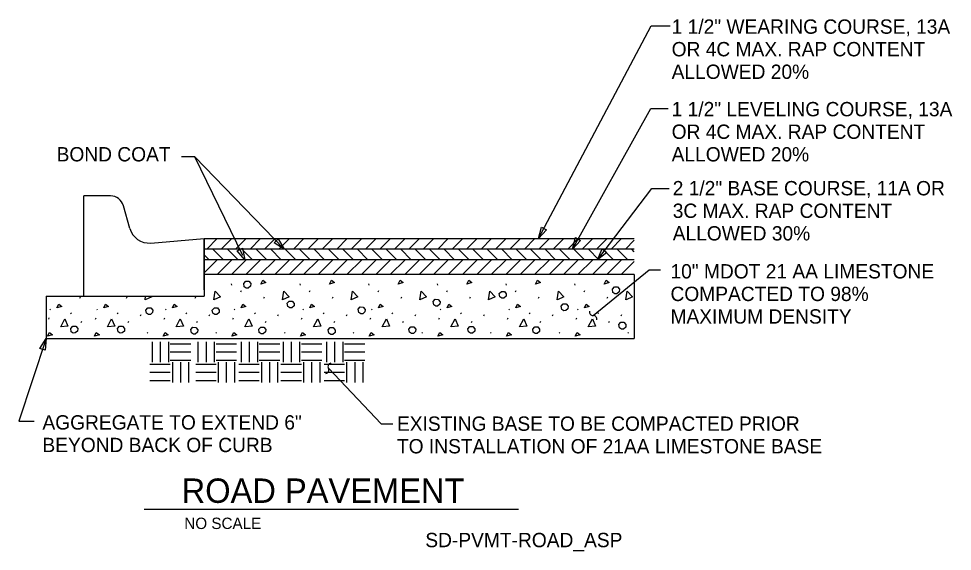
# Model space of a CAD drawing. Extents: x 9879.1 to 9947.1, y 9983.9 to 10022.7.
import ezdxf

# ---------------------------------------------------------------- set-up
doc = ezdxf.new("R2010")
doc.units = 0
for name, color, linetype in [('G-ANNO-TEXT', 7, 'Continuous'), ('G-DETL-LINE', 7, 'Continuous'), ('G-DETL-OTLN', 7, 'Continuous'), ('G-DETL-PATT', 7, 'Continuous')]:
    doc.layers.add(name, color=color, linetype=linetype)

msp = doc.modelspace()

# ---------------------------------------------------------------- linework, layer by layer
at = {"layer": 'G-ANNO-TEXT'}
for p, q in [((9892.6, 10005.594), (9892.6, 10006.669)), ((9892.6, 10004.685), (9892.6, 10005.594)), ((9888.222, 9986.949), (9915.472, 9986.949))]:
    msp.add_line(p, q, dxfattribs=at)
for points in [[(9916.941, 10006.675), (9925.138, 10022.152), (9926.513, 10022.152)], [(9919.408, 10005.906), (9925.121, 10016.137), (9926.384, 10016.137)], [(9895.409, 10005.432), (9891.922, 10012.612), (9890.939, 10012.612)], [(9898.415, 10005.898), (9891.922, 10012.612), (9891.922, 10012.612)], [(9921.247, 10005.132), (9925.193, 10010.313), (9926.437, 10010.313)]]:
    msp.add_lwpolyline(points, dxfattribs=at)
for points in [[(9917.515, 10007.314), (9916.941, 10006.675), (9917.147, 10007.509)], [(9897.985, 10006.642), (9898.415, 10005.898), (9897.686, 10006.352)], [(9919.997, 10006.532), (9919.408, 10005.906), (9919.633, 10006.735)], [(9895.38, 10005.969), (9895.557, 10005.128), (9895.006, 10005.787)], [(9921.908, 10005.659), (9921.237, 10005.123), (9921.577, 10005.912)]]:
    msp.add_lwpolyline(points, close=True, dxfattribs=at)
at = {"layer": 'G-DETL-LINE'}
for p, q in [((9892.6, 10006.669), (9923.906, 10006.669)), ((9923.906, 10005.899), (9892.6, 10005.899)), ((9923.906, 10005.128), (9892.6, 10005.128)), ((9923.906, 10004.054), (9892.6, 10004.054)), ((9923.906, 10004.054), (9923.906, 9999.397)), ((9881.093, 10002.467), (9881.093, 9999.397)), ((9881.093, 10002.467), (9883.832, 10002.467)), ((9881.093, 9999.397), (9923.906, 9999.397))]:
    msp.add_line(p, q, dxfattribs=at)
for points in [[(9920.908, 10001.064), (9924.979, 10004.38), (9925.807, 10004.38)], [(9881.093, 9999.397), (9879.087, 9993.37), (9880.204, 9993.37)], [(9901.636, 9997.221), (9905.48, 9993.165), (9906.339, 9993.165)]]:
    msp.add_lwpolyline(points, dxfattribs=at)
msp.add_lwpolyline([(9880.632, 9998.672), (9881.093, 9999.397), (9881.028, 9998.54)], close=True, dxfattribs=at)
for centre, start, end in [((9920.898, 10001.324), 166.03521, 272.29541), ((9920.918, 10000.804), 346.03521, 92.29541), ((9901.407, 9997.097), 281.95462, 28.21482), ((9901.866, 9997.344), 101.95462, 208.21482)]:
    msp.add_arc(centre, 0.26, start, end, dxfattribs=at)
at = {"layer": 'G-DETL-OTLN'}
for p, q in [((9885.775, 10009.774), (9883.832, 10009.774)), ((9883.832, 10002.467), (9883.832, 10009.774)), ((9887.175, 10007.408), (9886.714, 10009.062)), ((9888.704, 10006.344), (9892.6, 10006.669)), ((9892.6, 10002.923), (9892.6, 10006.669)), ((9892.6, 10006.669), (9892.6, 10002.467)), ((9883.832, 10002.467), (9892.6, 10002.467))]:
    msp.add_line(p, q, dxfattribs=at)
for centre, radius, start, end in [((9885.775, 10008.8), 0.974, 15.57142, 90), ((9888.582, 10007.801), 1.461, 195.57137, 274.76366)]:
    msp.add_arc(centre, radius, start, end, dxfattribs=at)
at = {"layer": 'G-DETL-PATT'}
for p, q in [((9892.78, 10005.899), (9893.55, 10006.669)), ((9893.831, 10005.899), (9894.601, 10006.669)), ((9894.882, 10005.899), (9895.652, 10006.669)), ((9895.933, 10005.899), (9896.703, 10006.669)), ((9896.984, 10005.899), (9897.755, 10006.669)), ((9898.035, 10005.899), (9898.806, 10006.669)), ((9899.087, 10005.899), (9899.857, 10006.669)), ((9900.138, 10005.899), (9900.908, 10006.669)), ((9901.189, 10005.899), (9901.959, 10006.669)), ((9902.24, 10005.899), (9903.01, 10006.669)), ((9903.291, 10005.899), (9904.061, 10006.669)), ((9904.342, 10005.899), (9905.113, 10006.669)), ((9905.393, 10005.899), (9906.164, 10006.669)), ((9906.445, 10005.899), (9907.215, 10006.669)), ((9907.496, 10005.899), (9908.266, 10006.669)), ((9908.547, 10005.899), (9909.317, 10006.669)), ((9909.598, 10005.899), (9910.368, 10006.669)), ((9910.649, 10005.899), (9911.419, 10006.669)), ((9911.7, 10005.899), (9912.47, 10006.669)), ((9912.751, 10005.899), (9913.522, 10006.669)), ((9913.802, 10005.899), (9914.573, 10006.669)), ((9914.854, 10005.899), (9915.624, 10006.669)), ((9915.905, 10005.899), (9916.675, 10006.669)), ((9916.956, 10005.899), (9917.726, 10006.669)), ((9918.007, 10005.899), (9918.777, 10006.669)), ((9919.058, 10005.899), (9919.828, 10006.669)), ((9920.109, 10005.899), (9920.88, 10006.669)), ((9921.16, 10005.899), (9921.931, 10006.669)), ((9922.212, 10005.899), (9922.982, 10006.669)), ((9894.006, 10005.128), (9893.235, 10005.899)), ((9895.057, 10005.128), (9894.286, 10005.899)), ((9896.108, 10005.128), (9895.338, 10005.899)), ((9897.159, 10005.128), (9896.389, 10005.899)), ((9898.21, 10005.128), (9897.44, 10005.899)), ((9899.261, 10005.128), (9898.491, 10005.899)), ((9900.313, 10005.128), (9899.542, 10005.899)), ((9901.364, 10005.128), (9900.593, 10005.899)), ((9902.415, 10005.128), (9901.644, 10005.899)), ((9903.466, 10005.128), (9902.696, 10005.899)), ((9904.517, 10005.128), (9903.747, 10005.899)), ((9905.568, 10005.128), (9904.798, 10005.899)), ((9906.619, 10005.128), (9905.849, 10005.899)), ((9907.671, 10005.128), (9906.9, 10005.899)), ((9908.722, 10005.128), (9907.951, 10005.899)), ((9909.773, 10005.128), (9909.002, 10005.899)), ((9910.824, 10005.128), (9910.054, 10005.899)), ((9911.875, 10005.128), (9911.105, 10005.899)), ((9912.926, 10005.128), (9912.156, 10005.899)), ((9913.977, 10005.128), (9913.207, 10005.899)), ((9915.028, 10005.128), (9914.258, 10005.899)), ((9916.08, 10005.128), (9915.309, 10005.899)), ((9917.131, 10005.128), (9916.36, 10005.899)), ((9918.182, 10005.128), (9917.411, 10005.899)), ((9919.233, 10005.128), (9918.462, 10005.899)), ((9920.284, 10005.128), (9919.514, 10005.899)), ((9921.335, 10005.128), (9920.565, 10005.899)), ((9922.386, 10005.128), (9921.616, 10005.899)), ((9923.437, 10005.128), (9922.667, 10005.899)), ((9923.263, 10005.899), (9923.906, 10006.542)), ((9923.906, 10005.711), (9923.718, 10005.899)), ((9892.955, 10005.128), (9892.6, 10005.482)), ((9892.6, 10004.179), (9893.55, 10005.128)), ((9893.527, 10004.054), (9894.601, 10005.128)), ((9894.578, 10004.054), (9895.652, 10005.128)), ((9895.629, 10004.054), (9896.703, 10005.128)), ((9896.68, 10004.054), (9897.755, 10005.128)), ((9897.731, 10004.054), (9898.806, 10005.128)), ((9898.782, 10004.054), (9899.857, 10005.128)), ((9899.834, 10004.054), (9900.908, 10005.128)), ((9900.885, 10004.054), (9901.959, 10005.128)), ((9901.936, 10004.054), (9903.01, 10005.128)), ((9902.987, 10004.054), (9904.061, 10005.128)), ((9904.038, 10004.054), (9905.113, 10005.128)), ((9905.089, 10004.054), (9906.164, 10005.128)), ((9906.14, 10004.054), (9907.215, 10005.128)), ((9907.192, 10004.054), (9908.266, 10005.128)), ((9908.243, 10004.054), (9909.317, 10005.128)), ((9909.294, 10004.054), (9910.368, 10005.128)), ((9910.345, 10004.054), (9911.419, 10005.128)), ((9911.396, 10004.054), (9912.47, 10005.128)), ((9912.447, 10004.054), (9913.522, 10005.128)), ((9913.498, 10004.054), (9914.573, 10005.128)), ((9914.549, 10004.054), (9915.624, 10005.128)), ((9915.601, 10004.054), (9916.675, 10005.128)), ((9916.652, 10004.054), (9917.726, 10005.128)), ((9917.703, 10004.054), (9918.777, 10005.128)), ((9918.754, 10004.054), (9919.828, 10005.128)), ((9919.805, 10004.054), (9920.88, 10005.128)), ((9920.856, 10004.054), (9921.931, 10005.128)), ((9921.907, 10004.054), (9922.982, 10005.128)), ((9922.958, 10004.054), (9923.906, 10005.001)), ((9894.565, 10003.366), (9894.576, 10003.266)), ((9899.565, 10003.366), (9899.576, 10003.266)), ((9904.565, 10003.366), (9904.576, 10003.266)), ((9909.565, 10003.366), (9909.576, 10003.266)), ((9914.565, 10003.366), (9914.576, 10003.266)), ((9919.565, 10003.366), (9919.576, 10003.266)), ((9895.257, 10002.777), (9895.301, 10002.877)), ((9900.257, 10002.777), (9900.301, 10002.877)), ((9905.257, 10002.777), (9905.301, 10002.877)), ((9910.257, 10002.777), (9910.301, 10002.877)), ((9915.257, 10002.777), (9915.301, 10002.877)), ((9920.257, 10002.777), (9920.301, 10002.877)), ((9883.532, 10002.322), (9883.577, 10002.422)), ((9886.944, 10002.322), (9886.988, 10002.422)), ((9891.944, 10002.322), (9891.988, 10002.422)), ((9896.944, 10002.322), (9896.988, 10002.422)), ((9901.944, 10002.322), (9901.988, 10002.422)), ((9906.944, 10002.322), (9906.988, 10002.422)), ((9911.944, 10002.322), (9911.988, 10002.422)), ((9916.944, 10002.322), (9916.988, 10002.422)), ((9921.944, 10002.322), (9921.988, 10002.422)), ((9881.358, 10001.534), (9881.403, 10001.468)), ((9882.854, 10001.252), (9882.898, 10001.185)), ((9884.77, 10001.534), (9884.814, 10001.468)), ((9886.265, 10001.252), (9886.309, 10001.185)), ((9887.954, 10001.035), (9887.998, 10001.134)), ((9889.77, 10001.534), (9889.814, 10001.468)), ((9891.265, 10001.252), (9891.309, 10001.185)), ((9892.954, 10001.035), (9892.998, 10001.134)), ((9894.77, 10001.534), (9894.814, 10001.468)), ((9896.265, 10001.252), (9896.309, 10001.185)), ((9897.954, 10001.035), (9897.998, 10001.134)), ((9899.77, 10001.534), (9899.814, 10001.468)), ((9901.265, 10001.252), (9901.309, 10001.185)), ((9902.954, 10001.035), (9902.998, 10001.134)), ((9904.77, 10001.534), (9904.814, 10001.468)), ((9906.265, 10001.252), (9906.309, 10001.185)), ((9907.954, 10001.035), (9907.998, 10001.134)), ((9909.77, 10001.534), (9909.814, 10001.468)), ((9911.265, 10001.252), (9911.309, 10001.185)), ((9912.954, 10001.035), (9912.998, 10001.134)), ((9914.77, 10001.534), (9914.814, 10001.468)), ((9916.265, 10001.252), (9916.309, 10001.185)), ((9917.954, 10001.035), (9917.998, 10001.134)), ((9919.77, 10001.534), (9919.814, 10001.468)), ((9921.265, 10001.252), (9921.294, 10001.208)), ((9921.301, 10001.198), (9921.309, 10001.185)), ((9922.954, 10001.035), (9922.998, 10001.134)), ((9881.274, 10000.803), (9881.319, 10000.903)), ((9883.643, 10000.547), (9883.688, 10000.647)), ((9884.686, 10000.803), (9884.73, 10000.903)), ((9887.055, 10000.547), (9887.099, 10000.647)), ((9889.686, 10000.803), (9889.73, 10000.903)), ((9892.055, 10000.547), (9892.099, 10000.647)), ((9894.686, 10000.803), (9894.73, 10000.903)), ((9897.055, 10000.547), (9897.099, 10000.647)), ((9899.686, 10000.803), (9899.73, 10000.903)), ((9902.055, 10000.547), (9902.099, 10000.647)), ((9904.686, 10000.803), (9904.73, 10000.903)), ((9907.055, 10000.547), (9907.099, 10000.647)), ((9909.686, 10000.803), (9909.73, 10000.903)), ((9912.055, 10000.547), (9912.099, 10000.647)), ((9914.686, 10000.803), (9914.73, 10000.903)), ((9917.055, 10000.547), (9917.099, 10000.647)), ((9919.686, 10000.803), (9919.73, 10000.903)), ((9922.055, 10000.547), (9922.099, 10000.647)), ((9888.442, 9999.837), (9888.487, 9999.77)), ((9893.442, 9999.837), (9893.487, 9999.77)), ((9898.442, 9999.837), (9898.487, 9999.77)), ((9903.442, 9999.837), (9903.487, 9999.77)), ((9908.442, 9999.837), (9908.487, 9999.77)), ((9913.442, 9999.837), (9913.487, 9999.77)), ((9918.442, 9999.837), (9918.487, 9999.77)), ((9923.442, 9999.837), (9923.487, 9999.77)), ((9888.804, 9999.143), (9888.804, 9997.661)), ((9889.397, 9999.143), (9889.397, 9997.661)), ((9889.99, 9999.143), (9889.99, 9997.661)), ((9892.134, 9999.143), (9892.134, 9997.661)), ((9892.727, 9999.143), (9892.727, 9997.661)), ((9893.32, 9999.143), (9893.32, 9997.661)), ((9895.284, 9999.143), (9895.284, 9997.661)), ((9895.877, 9999.143), (9895.877, 9997.661)), ((9896.47, 9999.143), (9896.47, 9997.661)), ((9898.345, 9999.143), (9898.345, 9997.661)), ((9898.938, 9999.143), (9898.938, 9997.661)), ((9899.531, 9999.143), (9899.531, 9997.661)), ((9901.495, 9999.143), (9901.495, 9997.661)), ((9902.088, 9999.143), (9902.088, 9997.661)), ((9902.681, 9999.143), (9902.681, 9997.661)), ((9890.127, 9999.005), (9891.61, 9999.005)), ((9890.127, 9998.412), (9891.61, 9998.412)), ((9893.457, 9999.005), (9894.94, 9999.005)), ((9893.457, 9998.412), (9894.94, 9998.412)), ((9896.608, 9999.005), (9898.09, 9999.005)), ((9896.608, 9998.412), (9898.09, 9998.412)), ((9899.668, 9999.005), (9901.15, 9999.005)), ((9899.668, 9998.412), (9901.15, 9998.412)), ((9902.818, 9999.005), (9904.301, 9999.005)), ((9902.818, 9998.412), (9904.301, 9998.412)), ((9890.127, 9997.819), (9891.61, 9997.819)), ((9893.457, 9997.819), (9894.94, 9997.819)), ((9896.608, 9997.819), (9898.09, 9997.819)), ((9899.668, 9997.819), (9901.15, 9997.819)), ((9902.818, 9997.819), (9904.301, 9997.819)), ((9888.645, 9997.523), (9890.127, 9997.523)), ((9890.276, 9997.671), (9890.276, 9996.189)), ((9890.869, 9997.671), (9890.869, 9996.189)), ((9891.461, 9997.671), (9891.461, 9996.189)), ((9891.975, 9997.523), (9893.457, 9997.523)), ((9893.606, 9997.671), (9893.606, 9996.189)), ((9894.199, 9997.671), (9894.199, 9996.189)), ((9894.792, 9997.671), (9894.792, 9996.189)), ((9895.125, 9997.523), (9896.608, 9997.523)), ((9896.756, 9997.671), (9896.756, 9996.189)), ((9897.349, 9997.671), (9897.349, 9996.189)), ((9897.942, 9997.671), (9897.942, 9996.189)), ((9898.185, 9997.523), (9899.668, 9997.523)), ((9899.816, 9997.671), (9899.816, 9996.189)), ((9900.409, 9997.671), (9900.409, 9996.189)), ((9901.002, 9997.671), (9901.002, 9996.189)), ((9901.336, 9997.523), (9902.818, 9997.523)), ((9902.966, 9997.671), (9902.966, 9996.189)), ((9903.559, 9997.671), (9903.559, 9996.189)), ((9904.152, 9997.671), (9904.152, 9996.189)), ((9888.645, 9996.93), (9890.127, 9996.93)), ((9891.975, 9996.93), (9893.457, 9996.93)), ((9895.125, 9996.93), (9896.608, 9996.93)), ((9898.185, 9996.93), (9899.668, 9996.93)), ((9901.336, 9996.93), (9902.818, 9996.93)), ((9888.645, 9996.337), (9890.127, 9996.337)), ((9891.975, 9996.337), (9893.457, 9996.337)), ((9895.125, 9996.337), (9896.608, 9996.337)), ((9898.185, 9996.337), (9899.668, 9996.337)), ((9901.336, 9996.337), (9902.818, 9996.337))]:
    msp.add_line(p, q, dxfattribs=at)
for points in [[(9895.512, 10003.162), (9895.471, 10003.398), (9895.618, 10003.562), (9895.838, 10003.558), (9895.979, 10003.385), (9895.963, 10003.209), (9895.799, 10003.067), (9895.656, 10003.065), (9895.513, 10003.162)], [(9896.724, 10003.349), (9896.857, 10003.627), (9897.079, 10003.46), (9896.724, 10003.349)], [(9901.724, 10003.349), (9901.857, 10003.627), (9902.079, 10003.46), (9901.724, 10003.349)], [(9906.724, 10003.349), (9906.857, 10003.627), (9907.079, 10003.46), (9906.724, 10003.349)], [(9911.724, 10003.349), (9911.857, 10003.627), (9912.079, 10003.46), (9911.724, 10003.349)], [(9916.724, 10003.349), (9916.857, 10003.627), (9917.079, 10003.46), (9916.724, 10003.349)], [(9921.724, 10003.349), (9921.857, 10003.627), (9922.079, 10003.46), (9921.724, 10003.349)], [(9893.294, 10002.207), (9893.382, 10002.842), (9893.78, 10002.431), (9893.305, 10002.211)], [(9898.294, 10002.207), (9898.382, 10002.842), (9898.78, 10002.431), (9898.305, 10002.211)], [(9903.294, 10002.207), (9903.382, 10002.842), (9903.78, 10002.431), (9903.305, 10002.211)], [(9908.294, 10002.207), (9908.382, 10002.842), (9908.78, 10002.431), (9908.305, 10002.211)], [(9913.294, 10002.207), (9913.382, 10002.842), (9913.78, 10002.431), (9913.305, 10002.211)], [(9914.122, 10002.42), (9914.081, 10002.656), (9914.228, 10002.82), (9914.448, 10002.816), (9914.589, 10002.644), (9914.573, 10002.468), (9914.408, 10002.326), (9914.266, 10002.323), (9914.122, 10002.42)], [(9918.294, 10002.207), (9918.382, 10002.842), (9918.78, 10002.431), (9918.305, 10002.211)], [(9922.357, 10002.75), (9922.316, 10002.986), (9922.462, 10003.15), (9922.682, 10003.146), (9922.824, 10002.973), (9922.807, 10002.797), (9922.643, 10002.655), (9922.501, 10002.653), (9922.357, 10002.75)], [(9923.294, 10002.207), (9923.382, 10002.842), (9923.78, 10002.431), (9923.305, 10002.211)], [(9881.867, 10001.612), (9882.001, 10001.889), (9882.223, 10001.723), (9881.867, 10001.612)], [(9885.279, 10001.612), (9885.412, 10001.889), (9885.634, 10001.723), (9885.279, 10001.612)], [(9888.294, 10002.207), (9888.33, 10002.467)], [(9888.745, 10002.467), (9888.78, 10002.431), (9888.305, 10002.211)], [(9890.279, 10001.612), (9890.412, 10001.889), (9890.634, 10001.723), (9890.279, 10001.612)], [(9895.279, 10001.612), (9895.412, 10001.889), (9895.634, 10001.723), (9895.279, 10001.612)], [(9898.683, 10001.72), (9898.642, 10001.956), (9898.788, 10002.12), (9899.008, 10002.116), (9899.15, 10001.944), (9899.133, 10001.768), (9898.969, 10001.625), (9898.827, 10001.623), (9898.683, 10001.72)], [(9900.279, 10001.612), (9900.412, 10001.889), (9900.634, 10001.723), (9900.279, 10001.612)], [(9905.279, 10001.612), (9905.412, 10001.889), (9905.634, 10001.723), (9905.279, 10001.612)], [(9909.305, 10001.843), (9909.264, 10002.079), (9909.41, 10002.244), (9909.631, 10002.24), (9909.772, 10002.067), (9909.756, 10001.891), (9909.591, 10001.749), (9909.449, 10001.747), (9909.305, 10001.844)], [(9910.279, 10001.612), (9910.412, 10001.889), (9910.634, 10001.723), (9910.279, 10001.612)], [(9915.279, 10001.612), (9915.412, 10001.889), (9915.634, 10001.723), (9915.279, 10001.612)], [(9918.631, 10001.514), (9918.59, 10001.75), (9918.736, 10001.914), (9918.956, 10001.91), (9919.097, 10001.738), (9919.081, 10001.562), (9918.917, 10001.419), (9918.775, 10001.417), (9918.631, 10001.514)], [(9920.279, 10001.612), (9920.412, 10001.889), (9920.634, 10001.723), (9920.279, 10001.612)], [(9888.39, 10001.226), (9888.349, 10001.461), (9888.495, 10001.626), (9888.715, 10001.622), (9888.856, 10001.449), (9888.84, 10001.273), (9888.676, 10001.131), (9888.533, 10001.129), (9888.39, 10001.226)], [(9893.227, 10001.226), (9893.186, 10001.461), (9893.333, 10001.626), (9893.553, 10001.622), (9893.694, 10001.449), (9893.678, 10001.273), (9893.514, 10001.131), (9893.371, 10001.129), (9893.227, 10001.226)], [(9903.85, 10001.287), (9903.809, 10001.523), (9903.955, 10001.687), (9904.175, 10001.683), (9904.317, 10001.511), (9904.301, 10001.335), (9904.136, 10001.193), (9903.994, 10001.191), (9903.85, 10001.287)], [(9882.145, 10000.248), (9882.445, 10000.814), (9882.678, 10000.292), (9882.156, 10000.248)], [(9885.556, 10000.248), (9885.856, 10000.814), (9886.089, 10000.292), (9885.567, 10000.248)], [(9890.556, 10000.248), (9890.856, 10000.814), (9891.089, 10000.292), (9890.567, 10000.248)], [(9895.556, 10000.248), (9895.856, 10000.814), (9896.089, 10000.292), (9895.567, 10000.248)], [(9900.556, 10000.248), (9900.856, 10000.814), (9901.089, 10000.292), (9900.567, 10000.248)], [(9905.556, 10000.248), (9905.856, 10000.814), (9906.089, 10000.292), (9905.567, 10000.248)], [(9910.556, 10000.248), (9910.856, 10000.814), (9911.089, 10000.292), (9910.567, 10000.248)], [(9915.556, 10000.248), (9915.856, 10000.814), (9916.089, 10000.292), (9915.567, 10000.248)], [(9920.556, 10000.248), (9920.856, 10000.814), (9921.089, 10000.292), (9920.567, 10000.248)], [(9922.83, 10000.175), (9922.789, 10000.411), (9922.936, 10000.575), (9923.156, 10000.571), (9923.297, 10000.399), (9923.281, 10000.223), (9923.116, 10000.08), (9922.974, 10000.078), (9922.83, 10000.175)], [(9881.197, 9999.548), (9881.33, 9999.826), (9881.552, 9999.659), (9881.197, 9999.548)], [(9882.92, 9999.887), (9882.879, 10000.123), (9883.025, 10000.287), (9883.245, 10000.283), (9883.386, 10000.11), (9883.37, 9999.934), (9883.206, 9999.792), (9883.063, 9999.79), (9882.92, 9999.887)], [(9884.608, 9999.548), (9884.741, 9999.826), (9884.963, 9999.659), (9884.608, 9999.548)], [(9886.331, 9999.887), (9886.29, 10000.123), (9886.436, 10000.287), (9886.657, 10000.283), (9886.798, 10000.11), (9886.782, 9999.934), (9886.617, 9999.792), (9886.475, 9999.79), (9886.331, 9999.887)], [(9889.608, 9999.548), (9889.741, 9999.826), (9889.963, 9999.659), (9889.608, 9999.548)], [(9891.663, 9999.804), (9891.622, 10000.04), (9891.768, 10000.204), (9891.988, 10000.201), (9892.13, 10000.028), (9892.114, 9999.852), (9891.949, 9999.71), (9891.807, 9999.708), (9891.663, 9999.804)], [(9894.608, 9999.548), (9894.741, 9999.826), (9894.963, 9999.659), (9894.608, 9999.548)], [(9896.603, 9999.825), (9896.562, 10000.061), (9896.709, 10000.225), (9896.929, 10000.221), (9897.07, 10000.049), (9897.054, 9999.873), (9896.89, 9999.73), (9896.747, 9999.728), (9896.604, 9999.825)], [(9899.608, 9999.548), (9899.741, 9999.826), (9899.963, 9999.659), (9899.608, 9999.548)], [(9901.668, 9999.784), (9901.627, 10000.02), (9901.773, 10000.184), (9901.993, 10000.18), (9902.135, 10000.007), (9902.118, 9999.831), (9901.954, 9999.689), (9901.812, 9999.687), (9901.668, 9999.784)], [(9904.608, 9999.548), (9904.741, 9999.826), (9904.963, 9999.659), (9904.608, 9999.548)], [(9907.535, 9999.846), (9907.494, 10000.081), (9907.64, 10000.246), (9907.86, 10000.242), (9908.002, 10000.069), (9907.985, 9999.893), (9907.821, 9999.751), (9907.679, 9999.749), (9907.535, 9999.846)], [(9909.608, 9999.548), (9909.741, 9999.826), (9909.963, 9999.659), (9909.608, 9999.548)], [(9911.837, 9999.866), (9911.796, 10000.102), (9911.943, 10000.266), (9912.163, 10000.262), (9912.304, 10000.09), (9912.288, 9999.914), (9912.123, 9999.772), (9911.981, 9999.769), (9911.837, 9999.866)], [(9914.608, 9999.548), (9914.741, 9999.826), (9914.963, 9999.659), (9914.608, 9999.548)], [(9916.551, 9999.846), (9916.51, 10000.081), (9916.657, 10000.246), (9916.877, 10000.242), (9917.018, 10000.069), (9917.002, 9999.893), (9916.838, 9999.751), (9916.695, 9999.749), (9916.552, 9999.846)], [(9919.608, 9999.548), (9919.741, 9999.826), (9919.963, 9999.659), (9919.608, 9999.548)]]:
    msp.add_lwpolyline(points, dxfattribs=at)

# ---------------------------------------------------------------- texts
at = {"layer": 'G-ANNO-TEXT'}
for s, height, p in [('1 1/2" WEARING COURSE, 13A ', 1.044, (9926.628, 10021.585)), ('OR 4C MAX. RAP CONTENT ', 1.044, (9926.628, 10019.941)), ('ALLOWED 20%', 1.044, (9926.628, 10018.297)), ('1 1/2" LEVELING COURSE, 13A ', 1.044, (9926.628, 10015.573)), ('OR 4C MAX. RAP CONTENT ', 1.044, (9926.628, 10013.929)), ('BOND COAT', 1.044, (9881.849, 10012.288)), ('ALLOWED 20%', 1.044, (9926.628, 10012.285)), ('2 1/2" BASE COURSE, 11A OR ', 1.044, (9926.706, 10009.816)), ('3C MAX. RAP CONTENT ', 1.044, (9926.706, 10008.172)), ('ALLOWED 30%', 1.044, (9926.706, 10006.528)), ('10" MDOT 21 AA LIMESTONE', 1.044, (9926.543, 10003.762)), ('COMPACTED TO 98%', 1.044, (9926.543, 10002.118)), ('MAXIMUM DENSITY', 1.044, (9926.543, 10000.474)), ('AGGREGATE TO EXTEND 6"', 1.044, (9880.817, 9992.758)), ('EXISTING BASE TO BE COMPACTED PRIOR ', 1.044, (9906.629, 9992.666)), ('BEYOND BACK OF CURB', 1.044, (9880.817, 9991.114)), ('TO INSTALLATION OF 21AA LIMESTONE BASE', 1.044, (9906.629, 9991.022)), ('ROAD PAVEMENT ', 1.776, (9890.953, 9987.418)), ('NO SCALE', 0.828, (9891.147, 9985.514)), ('SD-PVMT-ROAD_ASP', 1.044, (9908.692, 9984.19))]:
    msp.add_text(s, height=height, dxfattribs=at).set_placement(p)

doc.saveas('drawing.dxf')
